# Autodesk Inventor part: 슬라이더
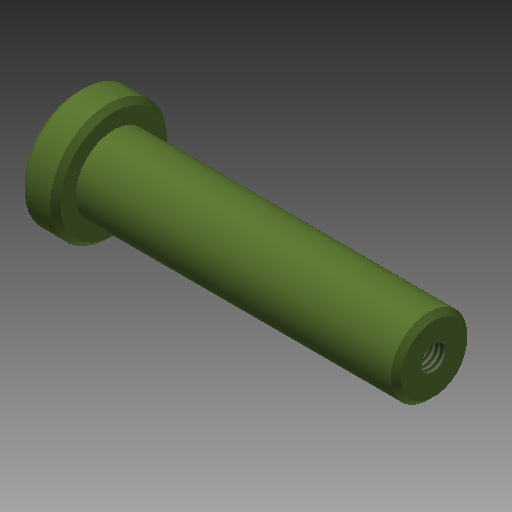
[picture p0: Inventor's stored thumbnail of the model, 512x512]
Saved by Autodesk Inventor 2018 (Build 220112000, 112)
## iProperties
Created: 2011-04
Part Number: 슬라이더
Document SubType Name: Modeling
Density: 1 g/cm^3
Material: 일반
Appearance: 올리브 녹색
Author: pww
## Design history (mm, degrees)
sketch "스케치1"
  geometry: L1 (-7, 0)-(63, 0); L2 (63, 0)-(63, 7.5); L3 (63, 7.5)-(0, 7.5); L4 (-7, 0)-(-7, 11.5); L5 (-7, 11.5)-(0, 11.5); L6 (0, 11.5)-(0, 7.5); 1 further point
  constraints: 12 end point, 3 perpendicular, 2 horizontal, 2 point on line, 1 parallel
  dimensions: "d1" = 70 distance of L1.start L1.end; "d19" = 15 diameter of L3 L1; "d20" = 7 distance of L4.end L5.end; "d21" = 23 diameter of L5 L1
revolve "회전1" stored, may be unused: angle "d4" = 90 deg
chamfer "모따기1" distance "d16" = 1; stored, may be unused: second distance "d17" = 2, angle "d18" = 45 deg
hole "구멍2" diameter "d24" = 4.917; stored, may be unused: countersink angle "d28" = 90 deg, drill point angle "d30" = 118 deg; dims "d22" = 10, "d23" = 10, "d25" = 10, "d26" = 4, "d27" = 2, "d29" = 13
node "솔리드1"
